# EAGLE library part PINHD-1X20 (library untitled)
PIN HEADER
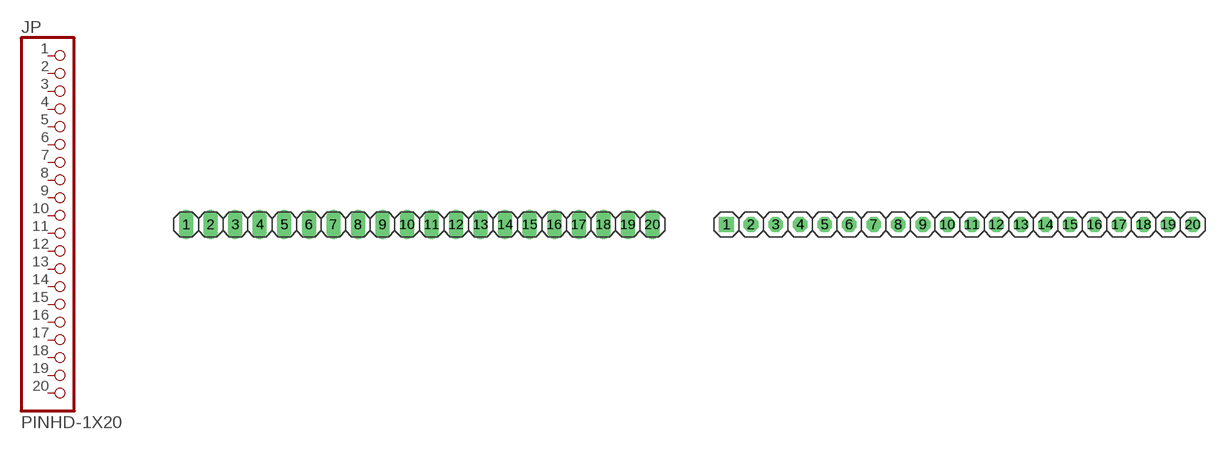
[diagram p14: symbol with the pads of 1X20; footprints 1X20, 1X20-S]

Designator prefix JP

## PINHD-1X20_2.54  [1X20]
1  1  pas
2  2  pas
3  3  pas
4  4  pas
5  5  pas
6  6  pas
7  7  pas
8  8  pas
9  9  pas
10  10  pas
11  11  pas
12  12  pas
13  13  pas
14  14  pas
15  15  pas
16  16  pas
17  17  pas
18  18  pas
19  19  pas
20  20  pas

## PINHD-1X20_2.54-S  [1X20-S]
Pads as for 1X20

## PINHD-1X20_2.54-90°  [1X20/90]
Pads as for 1X20

## PINHD-1X20_2.54-90°-S  [1X20/90-S]
Pads as for 1X20

## PINHD-1X20_2.00  [1X20M]
Pads as for 1X20

## PINHD-1X20_2.54-SMD  [1X20SMD]
Pads as for 1X20

## PINHD-1X20_2.54-SMD-90°  [1X20SMD/90]
Pads as for 1X20

## Footprint 1X20 (pad centres in mm)
PIN HEADER - 2.54
drill 1.016 long: 1 -24.13,0; 2 -21.59,0; 3 -19.05,0; 4 -16.51,0; 5 -13.97,0; 6 -11.43,0; 7 -8.89,0; 8 -6.35,0; 9 -3.81,0; 10 -1.27,0; 11 1.27,0; 12 3.81,0; 13 6.35,0; 14 8.89,0; 15 11.43,0; 16 13.97,0; 17 16.51,0; 18 19.05,0; 19 21.59,0; 20 24.13,0

## Footprint 1X20-S (pad centres in mm)
PIN HEADER - 2.54
drill 1.016 square: 1 -24.13,0
drill 1.016 octagon: 2 -21.59,0; 3 -19.05,0; 4 -16.51,0; 5 -13.97,0; 6 -11.43,0; 7 -8.89,0; 8 -6.35,0; 9 -3.81,0; 10 -1.27,0; 11 1.27,0; 12 3.81,0; 13 6.35,0; 14 8.89,0; 15 11.43,0; 16 13.97,0; 17 16.51,0; 18 19.05,0; 19 21.59,0; 20 24.13,0

## Footprint 1X20/90 (pad centres in mm)
PIN HEADER - 2.54 90°
drill 1.016 long: 1 -24.13,-3.81; 2 -21.59,-3.81; 3 -19.05,-3.81; 4 -16.51,-3.81; 5 -13.97,-3.81; 6 -11.43,-3.81; 7 -8.89,-3.81; 8 -6.35,-3.81; 9 -3.81,-3.81; 10 -1.27,-3.81; 11 1.27,-3.81; 12 3.81,-3.81; 13 6.35,-3.81; 14 8.89,-3.81; 15 11.43,-3.81; 16 13.97,-3.81; 17 16.51,-3.81; 18 19.05,-3.81; 19 21.59,-3.81; 20 24.13,-3.81

## Footprint 1X20/90-S (pad centres in mm)
PIN HEADER - 2.54 90°
drill 1.016 square: 1 -24.13,-3.81
drill 1.016 octagon: 2 -21.59,-3.81; 3 -19.05,-3.81; 4 -16.51,-3.81; 5 -13.97,-3.81; 6 -11.43,-3.81; 7 -8.89,-3.81; 8 -6.35,-3.81; 9 -3.81,-3.81; 10 -1.27,-3.81; 11 1.27,-3.81; 12 3.81,-3.81; 13 6.35,-3.81; 14 8.89,-3.81; 15 11.43,-3.81; 16 13.97,-3.81; 17 16.51,-3.81; 18 19.05,-3.81; 19 21.59,-3.81; 20 24.13,-3.81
